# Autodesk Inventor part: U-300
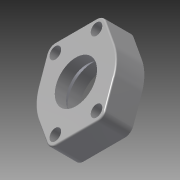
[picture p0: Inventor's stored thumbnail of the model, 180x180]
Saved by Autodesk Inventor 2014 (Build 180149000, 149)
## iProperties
Created: 2011-01
Part Number: U-300
Material: Steel
Document SubType Name: Modeling
Designer: deckm
Density: 7.85 g/cm^3
Description: FLARED FLANGE SAE WITH CLEARANCE HOLES
Mass: 259.498 g
Surface Area: 100.719 cm^2
Volume: 33.0571 cm^3
Appearance: Steel
Author: deckm
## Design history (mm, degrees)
derived "union_cap.ipt"
body "Solid1"
feature "Solid1::union_cap.ipt"
tag "TaggingFeature1"
other parameters: "d1" = 134.112, "d3" = 19.10263, "d25" = 61.976, "FilletTop" = 2, "d27" = 38.1, "d28" = 37 deg, "d29" = 42.418, "d30" = 31.75, "FilletCorners" = 13.843, "FilletEnds" = 65.532, "d8" = 42.418, "d9" = 0, "d12" = 17.4625, "d21" = 61.976, "d24" = 106.426
